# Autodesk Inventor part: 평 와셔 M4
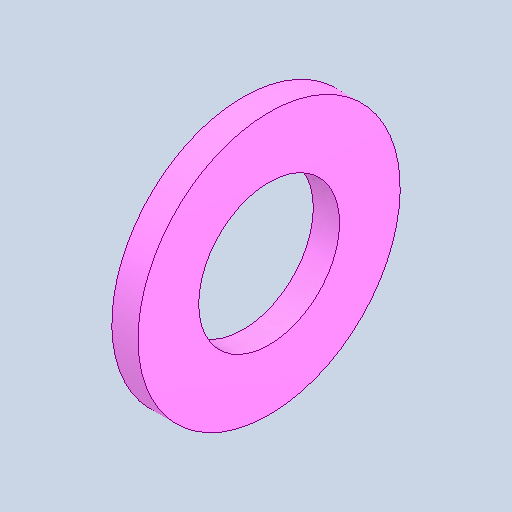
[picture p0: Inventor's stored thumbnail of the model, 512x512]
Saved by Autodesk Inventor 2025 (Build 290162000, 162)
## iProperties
Created: 2026-03
Part Number: 평 와셔 M4
Material: 강철, 연강
Description: 평면 와셔
Document SubType Name: Modeling
Designer: KDI
Density: 7.85 g/cm^3
Appearance: 기본값
Author: jhkim
Sending System: Autodesk Inventor 2026
Preprocessor: ST-DEVELOPER v20.1
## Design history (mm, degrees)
feature "Solid1"
node "솔리드1"
